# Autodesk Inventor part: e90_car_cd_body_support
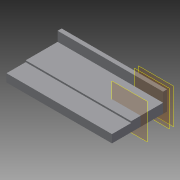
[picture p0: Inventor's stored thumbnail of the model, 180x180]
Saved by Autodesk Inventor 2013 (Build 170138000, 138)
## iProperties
Created: 2013-05
Part Number: e90_car_cd_body_support
Material: Generic
Document SubType Name: Modeling
Designer: claudiu
Density: 1 g/cm^3
Author: claudiu
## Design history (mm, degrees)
workplane "Work Plane9"
sketch "Sketch3"
  geometry: L1 (6.994, -4.785)-(-59.006, -4.785) reference; L2 (6.994, 98.215)-(6.994, -4.785) reference; L3 (-59.006, -4.785)-(-59.006, 98.215) reference; L4 (-59.006, -4.785)-(-59.006, 7.215); L5 (-59.006, 7.215)-(6.994, 7.215); L6 (6.994, -4.785)-(6.994, 7.215); L7 (6.994, -4.785)-(-59.006, -4.785); 1 further point
  constraints: 8 end point, 2 collinear, 2 point on line, 1 perpendicular
  dimensions: "d14" = 12 distance of L1.end L4.end
extrude "Extrusion3" join sketch "Sketch3" distance "d15" = 2.5; taper "d16" = 0 deg
workplane "Work Plane8"
sketch "Sketch4"
  geometry: L1 (-59.006, -4.785)-(6.994, -4.785) reference; L2 (6.994, -4.785)-(6.994, 7.215) reference; L3 (-59.006, 7.215)-(-59.006, -4.785) reference; L4 (-59.006, -4.785)-(-59.006, 1.215); L5 (-59.006, 1.215)-(6.994, 1.215); L6 (6.994, 1.215)-(6.994, -4.785); L7 (6.994, -4.785)-(-59.006, -4.785); 1 further point
  constraints: 8 end point, 2 midpoint, 1 collinear
  dimensions: "d17" = 6 distance of L1.start L4.end
extrude "Extrusion4" join sketch "Sketch4" distance "d18" = 20; taper "d19" = 0 deg
workplane "Work Plane10"
sketch "Sketch5"
  geometry: L1 (-59.006, -4.785)-(6.994, -4.785) reference; L2 (-59.006, -4.785)-(-59.006, 0.215); L3 (6.994, -4.785)-(6.994, 0.215); L4 (6.994, 0.215)-(-59.006, 0.215); L5 (-59.006, -4.785)-(6.994, -4.785); L6 (-59.006, -4.785)-(-59.006, 0.715); L7 (-59.006, 0.715)-(6.994, 0.715); L8 (6.994, 0.715)-(6.994, -4.785); 1 further point
  constraints: 14 end point, 1 collinear, 1 parallel, 1 perpendicular
  dimensions: "d20" = 5 distance of L1.start L2.end; "d21" = 5 distance of L1.end L3.end; "d24" = 5.5 distance of L1.start L6.end
extrude "Extrusion5" join sketch "Sketch5" distance "d22" = 18; taper "d23" = 0 deg
body "Solid1"
